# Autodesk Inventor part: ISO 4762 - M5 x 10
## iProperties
Comments: To add or edit properties for Autodesk Inventor files, use iProperties.
Created: 2004-08
Part Number: ISO 4762 - M5 x 10
Vendor: Autodesk Inc.
Document SubType Name: Modeling
Designer: John Blackburn
Material: Default
Description: Hexagon Socket Head Cap Screw
Standard: ISO 4762
Size Designation: M5 x 10
Alert: To add or edit properties for Autodesk Inventor files, use iProperties.
Control State: 0
Master: False
Checked Out: False
Shininess: 64.0
Length Units: 11269
Angle Units: 11279
Time Units: 11290
Mass Units: 11283
Length Display Precision: 3
Angle Display Precision: 2
Compacted: True
EGR: 1
Density: 0.0
Volumn: 0.0
Area: 0.0
PropertySet Name: Model Information
Author: John Blackburn
Revision Number: 8
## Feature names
1. Body [Revolution]
2. Slot [Extrusion]
3. Fillet1
4. Chamfer1
